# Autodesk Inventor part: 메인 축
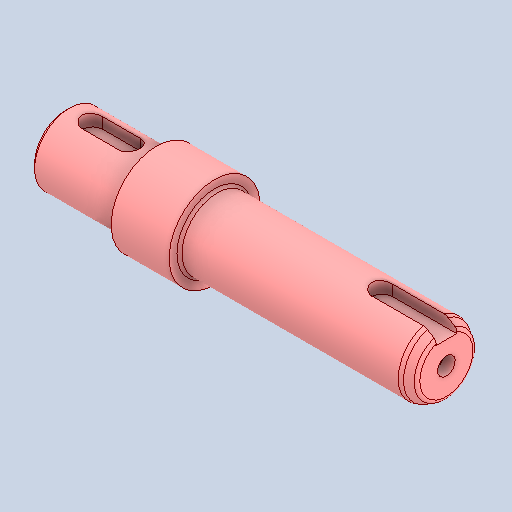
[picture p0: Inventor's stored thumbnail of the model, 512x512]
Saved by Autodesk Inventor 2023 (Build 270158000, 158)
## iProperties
Created: 2025-04
Part Number: 메인 축
Material: 강철, 탄소
Document SubType Name: Modeling
Designer: ADMIN_PC
Density: 7.85 g/cm^3
Appearance: 기본값
Author: jhkim
Sending System: Autodesk Inventor 2026
Preprocessor: ST-DEVELOPER v20.1
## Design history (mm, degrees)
feature "솔리드1"
node "솔리드2"
